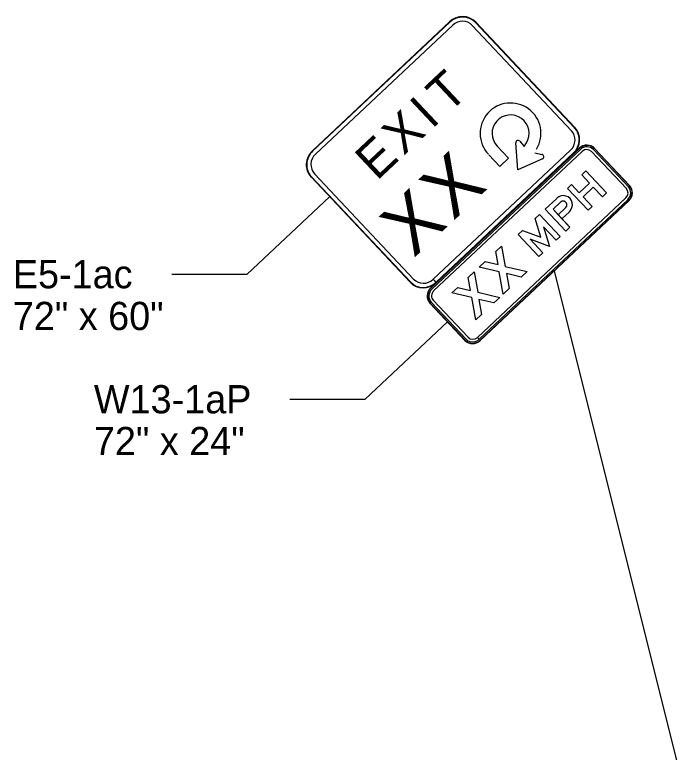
# Model space of a CAD drawing. Extents: x 571683 to 574814, y 1530838 to 1532905.
# Drawn here: x 572634.3 to 573075, y 1532381.2 to 1532870.7 of the extents above; entities that cross this region are included whole.
import ezdxf

# ---------------------------------------------------------------- set-up
doc = ezdxf.new("R2010")
doc.units = 0
for name, color, linetype in [('SignDetail', 7, 'Continuous'), ('SignPanel', 7, 'Continuous'), ('TextLabel', 7, 'Continuous')]:
    doc.layers.add(name, color=color, linetype=linetype)

msp = doc.modelspace()

# ---------------------------------------------------------------- linework, layer by layer
at = {"layer": 'SignDetail'}
for p, q in [((572788.5, 1532698.51), (572843.12, 1532749.91)), ((572738.5, 1532698.51), (572788.5, 1532698.51)), ((573132.85, 1532137.75), (572992.32, 1532700.81)), ((572866.63, 1532615.49), (572921.25, 1532666.89)), ((572816.63, 1532615.49), (572866.63, 1532615.49))]:
    msp.add_line(p, q, dxfattribs=at)
at = {"layer": 'SignPanel'}
for p, q in [((572922.7, 1532865.98), (572831.67, 1532780.32)), ((572922.7, 1532865.98), (572831.67, 1532780.32)), ((572922.7, 1532865.98), (572831.67, 1532780.32)), ((572831.87, 1532780.1), (572922.91, 1532865.77)), ((572833.72, 1532778.14), (572924.76, 1532863.8)), ((572937.75, 1532863.67), (573003.54, 1532793.76)), ((572939.8, 1532865.6), (573005.59, 1532795.68)), ((573005.82, 1532795.9), (572940.03, 1532865.81)), ((573005.82, 1532795.9), (572940.03, 1532865.81)), ((573005.82, 1532795.9), (572940.03, 1532865.81)), ((572967.96, 1532767.87), (572966.55, 1532785.63)), ((572969.32, 1532786.77), (572972.25, 1532783.29)), ((572972.25, 1532783.29), (572973.63, 1532785.6)), ((573008.66, 1532782.1), (572910.19, 1532689.43)), ((573008.66, 1532782.1), (572910.19, 1532689.43)), ((572910.3, 1532689.3), (573008.78, 1532781.97)), ((573009.41, 1532781.3), (572910.93, 1532688.63)), ((573002.88, 1532780.78), (572911.87, 1532695.14)), ((572912.13, 1532687.36), (573010.61, 1532780.03)), ((572954.18, 1532783.53), (572961.77, 1532775.46)), ((573016.75, 1532779.96), (573039.92, 1532755.34)), ((573041.25, 1532756.59), (573018.08, 1532781.21)), ((573018.77, 1532781.87), (573041.95, 1532757.24)), ((573042.08, 1532757.37), (573018.91, 1532781.99)), ((573042.08, 1532757.37), (573018.91, 1532781.99)), ((573004.73, 1532778.81), (572913.7, 1532693.15)), ((572913.9, 1532692.93), (573004.94, 1532778.59)), ((572913.9, 1532692.93), (573004.94, 1532778.59)), ((572913.93, 1532692.95), (573004.94, 1532778.59)), ((572956.01, 1532770.03), (572948.79, 1532777.7)), ((572984.26, 1532775.06), (572967.96, 1532767.87)), ((572979.23, 1532779.02), (572983.95, 1532778.04)), ((572898.85, 1532695.24), (572833.06, 1532765.16)), ((572830.79, 1532763.02), (572896.58, 1532693.1)), ((572830.79, 1532763.02), (572896.58, 1532693.1)), ((572830.79, 1532763.02), (572896.58, 1532693.1)), ((572896.8, 1532693.32), (572831.02, 1532763.23)), ((573039.61, 1532749.21), (572941.14, 1532656.56)), ((572942.34, 1532655.28), (573040.81, 1532747.94)), ((573041.44, 1532747.27), (572942.96, 1532654.6)), ((572943.08, 1532654.47), (573041.56, 1532747.14)), ((572943.08, 1532654.47), (573041.56, 1532747.14)), ((572991.3, 1532741.59), (572996.23, 1532746.23)), ((572991.3, 1532741.59), (572996.23, 1532746.23)), ((572991.3, 1532741.59), (572996.23, 1532746.23)), ((572997.19, 1532735.33), (573002.13, 1532739.97)), ((572913.9, 1532692.93), (572911.85, 1532695.12)), ((572911.87, 1532695.14), (572913.93, 1532692.95)), ((572913.9, 1532692.93), (572913.7, 1532693.15)), ((572913.7, 1532693.15), (572913.9, 1532692.93)), ((572909.66, 1532679.2), (572932.84, 1532654.57)), ((572909.66, 1532679.2), (572932.84, 1532654.57)), ((572932.97, 1532654.7), (572909.8, 1532679.32)), ((572910.49, 1532679.98), (572933.67, 1532655.35)), ((572934.99, 1532656.6), (572911.82, 1532681.23)), ((572942.33, 1532655.27), (572941.13, 1532656.54)), ((572941.14, 1532656.56), (572942.34, 1532655.28)), ((572943.08, 1532654.47), (572942.96, 1532654.6)), ((572942.96, 1532654.6), (572943.08, 1532654.47))]:
    msp.add_line(p, q, dxfattribs=at)
for points in [[(572961.77, 1532775.46), (572956.01, 1532770.03)], [(572993.76, 1532748.85), (572986.1, 1532741.64), (572999.81, 1532727.08), (573002.54, 1532729.65), (572997.19, 1532735.33)], [(572993.76, 1532748.85), (572986.1, 1532741.64), (572999.81, 1532727.08), (573002.54, 1532729.65), (572991.3, 1532741.59)], [(572993.76, 1532748.85), (572986.1, 1532741.64), (572999.81, 1532727.08), (573002.54, 1532729.65), (572991.3, 1532741.59)], [(572999.66, 1532742.59), (572994.73, 1532737.95), (572991.3, 1532741.59)], [(572999.66, 1532742.59), (572994.73, 1532737.95), (572997.2, 1532735.33), (573002.13, 1532739.97)], [(572999.66, 1532742.59), (572994.73, 1532737.95), (572997.2, 1532735.33), (573002.13, 1532739.97)]]:
    msp.add_lwpolyline(points, dxfattribs=at)
for points in [[(573015.56, 1532758.93), (573008.73, 1532752.5), (573003.52, 1532758.04), (573000.79, 1532755.47), (573014.5, 1532740.9), (573017.23, 1532743.47), (573011.2, 1532749.88), (573018.03, 1532756.3), (573024.06, 1532749.9), (573026.79, 1532752.47), (573013.08, 1532767.03), (573010.35, 1532764.46)], [(573015.56, 1532758.93), (573008.73, 1532752.5), (573003.52, 1532758.04), (573000.79, 1532755.47), (573014.5, 1532740.9), (573017.23, 1532743.47), (573011.2, 1532749.88), (573018.03, 1532756.3), (573024.06, 1532749.9), (573026.79, 1532752.47), (573013.08, 1532767.03), (573010.35, 1532764.46)], [(573015.56, 1532758.93), (573008.73, 1532752.5), (573003.52, 1532758.04), (573000.79, 1532755.47), (573014.5, 1532740.9), (573017.23, 1532743.47), (573011.2, 1532749.88), (573018.03, 1532756.3), (573024.06, 1532749.9), (573026.79, 1532752.47), (573013.08, 1532767.03), (573010.35, 1532764.46)], [(572983.26, 1532723.02), (572979.49, 1532735.42), (572982.43, 1532738.19), (572996.14, 1532723.62), (572993.4, 1532721.05), (572985.04, 1532729.94), (572989, 1532716.91), (572976.24, 1532721.66), (572984.6, 1532712.77), (572981.87, 1532710.2), (572968.17, 1532724.77), (572971.11, 1532727.53)], [(572983.26, 1532723.02), (572979.49, 1532735.42), (572982.43, 1532738.19), (572996.14, 1532723.62), (572993.4, 1532721.05), (572985.04, 1532729.94), (572989, 1532716.91), (572976.24, 1532721.66), (572984.6, 1532712.77), (572981.87, 1532710.2), (572968.17, 1532724.77), (572971.11, 1532727.53)], [(572983.26, 1532723.02), (572979.49, 1532735.42), (572982.43, 1532738.19), (572996.14, 1532723.62), (572993.4, 1532721.05), (572985.04, 1532729.94), (572989, 1532716.91), (572976.24, 1532721.66), (572984.6, 1532712.77), (572981.87, 1532710.2), (572968.17, 1532724.77), (572971.11, 1532727.53)], [(572970.27, 1532696.54), (572960.39, 1532698.92), (572962.17, 1532688.91), (572958.3, 1532685.27), (572955.67, 1532700.06), (572942.4, 1532703.27), (572946.27, 1532706.91), (572954.82, 1532704.84), (572953.28, 1532713.5), (572957.15, 1532717.14), (572959.54, 1532703.7), (572974.14, 1532700.18)], [(572970.27, 1532696.54), (572960.39, 1532698.92), (572962.17, 1532688.91), (572958.3, 1532685.27), (572955.67, 1532700.06), (572942.4, 1532703.27), (572946.27, 1532706.91), (572954.82, 1532704.84), (572953.28, 1532713.5), (572957.15, 1532717.14), (572959.54, 1532703.7), (572974.14, 1532700.18)], [(572970.27, 1532696.54), (572960.39, 1532698.92), (572962.17, 1532688.91), (572958.3, 1532685.27), (572955.67, 1532700.06), (572942.4, 1532703.27), (572946.27, 1532706.91), (572954.82, 1532704.84), (572953.28, 1532713.5), (572957.15, 1532717.14), (572959.54, 1532703.7), (572974.14, 1532700.18)], [(572952.06, 1532679.4), (572942.18, 1532681.78), (572943.96, 1532671.78), (572940.09, 1532668.13), (572937.46, 1532682.92), (572924.19, 1532686.13), (572928.06, 1532689.77), (572936.61, 1532687.7), (572935.07, 1532696.36), (572938.93, 1532700), (572941.33, 1532686.56), (572955.93, 1532683.04)], [(572952.06, 1532679.4), (572942.18, 1532681.78), (572943.96, 1532671.78), (572940.09, 1532668.13), (572937.46, 1532682.92), (572924.19, 1532686.13), (572928.06, 1532689.77), (572936.61, 1532687.7), (572935.07, 1532696.36), (572938.93, 1532700), (572941.33, 1532686.56), (572955.93, 1532683.04)], [(572952.06, 1532679.4), (572942.18, 1532681.78), (572943.96, 1532671.78), (572940.09, 1532668.13), (572937.46, 1532682.92), (572924.19, 1532686.13), (572928.06, 1532689.77), (572936.61, 1532687.7), (572935.07, 1532696.36), (572938.93, 1532700), (572941.33, 1532686.56), (572955.93, 1532683.04)]]:
    msp.add_lwpolyline(points, close=True, dxfattribs=at)
for centre, radius, start, end in [((572963.12, 1532791.94), 20.19, 328.8956, 223.2586), ((572963.12, 1532791.94), 12.27, 328.8956, 223.2586), ((572968.12, 1532785.76), 1.57, 40.105, 184.5301), ((572983.63, 1532776.5), 1.57, 293.8014, 78.2265)]:
    msp.add_arc(centre, radius, start, end, dxfattribs=at)
for centre, major_axis, ratio, start_param, end_param in [((572930.92, 1532857.24), (9.1, 8.57), 0.96, 0, 1.570796), ((572930.92, 1532857.24), (9.1, 8.57), 0.96, 0, 1.570796), ((572930.92, 1532857.24), (9.1, 8.57), 0.96, 0, 1.570796), ((572930.92, 1532857.24), (8.88, 8.35), 0.96, 0, 1.570796), ((572930.92, 1532857.24), (6.83, 6.42), 0.96, 0, 1.570796), ((572996.71, 1532787.33), (8.88, 8.35), 0.96, 4.712389, 6.283185), ((572996.71, 1532787.33), (9.1, 8.57), 0.96, 4.712389, 6.283185), ((572996.71, 1532787.33), (9.1, 8.57), 0.96, 4.712389, 6.283185), ((572996.71, 1532787.33), (9.1, 8.57), 0.96, 4.712389, 6.283185), ((572996.71, 1532787.33), (6.83, 6.42), 0.96, 4.712389, 6.283185), ((573013.53, 1532776.93), (5.38, 5.06), 0.96, 0, 1.570796), ((573013.53, 1532776.93), (5.38, 5.06), 0.96, 0, 1.570796), ((573013.53, 1532776.93), (5.25, 4.94), 0.96, 0, 1.570796), ((572839.89, 1532771.58), (9.1, 8.57), 0.96, 1.570796, 3.141593), ((572839.89, 1532771.58), (9.1, 8.57), 0.96, 1.570796, 3.141593), ((572839.89, 1532771.58), (9.1, 8.57), 0.96, 1.570796, 3.141593), ((572839.89, 1532771.58), (8.88, 8.35), 0.96, 1.570796, 3.141593), ((573013.53, 1532776.93), (4.55, 4.28), 0.96, 0, 1.570796), ((573013.53, 1532776.93), (3.22, 3.03), 0.96, 0, 1.570796), ((572839.89, 1532771.58), (6.83, 6.42), 0.96, 1.570796, 3.141593), ((573036.7, 1532752.31), (3.22, 3.03), 0.96, 4.712389, 6.283185), ((573036.7, 1532752.31), (4.55, 4.28), 0.96, 4.712389, 6.283185), ((573036.7, 1532752.31), (5.25, 4.94), 0.96, 4.712389, 6.283185), ((573036.7, 1532752.31), (5.38, 5.06), 0.96, 4.712389, 6.283185), ((573036.7, 1532752.31), (5.38, 5.06), 0.96, 4.712389, 6.283185), ((572997.95, 1532744.41), (4.63, 4.35), 0.960006, 4.712389, 7.853982), ((572997.95, 1532744.41), (4.63, 4.35), 0.960006, 4.712389, 7.853982), ((572997.95, 1532744.41), (4.63, 4.35), 0.960006, 4.712389, 7.853982), ((572997.95, 1532744.41), (1.9, 1.78), 0.960006, 4.712389, 7.853982), ((572997.95, 1532744.41), (1.9, 1.78), 0.960006, 4.712389, 7.853982), ((572997.95, 1532744.41), (1.9, 1.78), 0.960006, 4.712389, 7.853982), ((572905.68, 1532701.67), (9.1, 8.57), 0.96, 3.141593, 4.712389), ((572905.68, 1532701.67), (9.1, 8.57), 0.96, 3.141593, 4.712389), ((572905.68, 1532701.67), (9.1, 8.57), 0.96, 3.141593, 4.712389), ((572905.68, 1532701.67), (8.88, 8.35), 0.96, 3.141593, 4.712389), ((572905.68, 1532701.67), (6.83, 6.42), 0.96, 3.141593, 4.712389), ((572915.05, 1532684.26), (5.38, 5.06), 0.96, 1.570796, 3.141593), ((572915.05, 1532684.26), (5.38, 5.06), 0.96, 1.570796, 3.141593), ((572915.05, 1532684.26), (5.25, 4.94), 0.96, 1.570796, 3.141593), ((572915.05, 1532684.26), (4.55, 4.28), 0.96, 1.570796, 3.141593), ((572915.05, 1532684.26), (3.22, 3.03), 0.96, 1.570796, 3.141593), ((572938.22, 1532659.64), (5.38, 5.06), 0.96, 3.141593, 4.712389), ((572938.22, 1532659.64), (5.38, 5.06), 0.96, 3.141593, 4.712389), ((572938.22, 1532659.64), (5.25, 4.94), 0.96, 3.141593, 4.712389), ((572938.22, 1532659.64), (4.55, 4.28), 0.96, 3.141593, 4.712389), ((572938.22, 1532659.64), (3.22, 3.03), 0.96, 3.141593, 4.712389)]:
    msp.add_ellipse(centre, major_axis=major_axis, ratio=ratio, start_param=start_param, end_param=end_param, dxfattribs=at)

# ---------------------------------------------------------------- texts
for s, height, p in [('T', 24, (572921.68, 1532804.61)), ('I', 24, (572910.83, 1532794.4)), ('I', 24, (572910.83, 1532794.4)), ('X', 24, (572892.21, 1532776.88)), ('X', 24, (572892.21, 1532776.88)), ('E', 24, (572874.38, 1532760.1)), ('E', 24, (572874.38, 1532760.1)), ('X', 36, (572925.04, 1532733.61)), ('X', 36, (572925.04, 1532733.61)), ('X', 36, (572898.82, 1532708.94)), ('X', 36, (572898.82, 1532708.94))]:
    msp.add_text(s, height=height, rotation=43.2586, dxfattribs=at).set_placement(p)
at = {"layer": 'TextLabel'}
for s, p in [('E5-1ac', (572633.01, 1532689.14)), ('72" x 60"', (572633.01, 1532661.4)), ('W13-1aP', (572686.79, 1532606.12)), ('72" x 24"', (572686.79, 1532578.38))]:
    msp.add_text(s, height=18.74, dxfattribs=at).set_placement(p)

doc.saveas('drawing.dxf')
